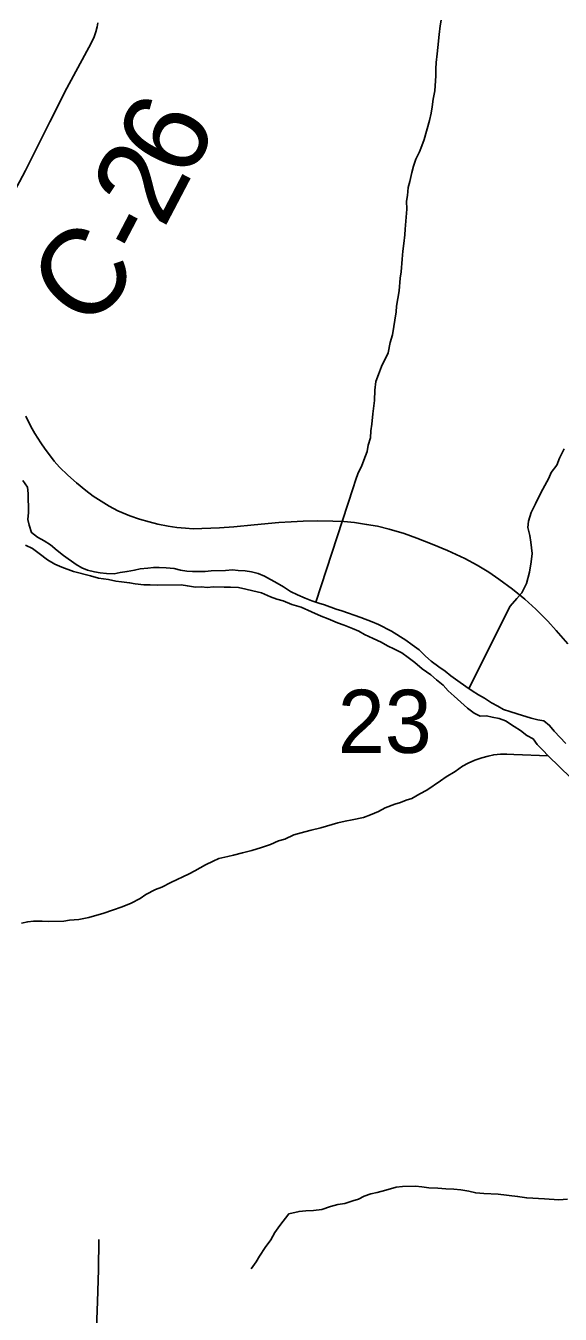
# Model space of a CAD drawing. Extents: x -3.3 to 34, y 0 to 56.8.
# Drawn here: x -2.155 to -1.801, y 31.825 to 32.678 of the extents above; entities that cross this region are included whole.
import ezdxf

# ---------------------------------------------------------------- set-up
doc = ezdxf.new("R2010")
doc.units = 0
for name, color, linetype in [('GM_X_County_Road', 7, 'Continuous'), ('GM_X_Major_River', 7, 'Continuous'), ('GM_X_Section_Text', 7, 'Continuous'), ('GM_X_State_Route', 7, 'Continuous'), ('GM_X_Township_Road', 7, 'Continuous'), ('GT_Project_Soil_Layers', 7, 'Continuous'), ('SH_Masking', 7, 'Continuous')]:
    doc.layers.add(name, color=color, linetype=linetype)

msp = doc.modelspace()

# ---------------------------------------------------------------- linework, layer by layer
at = {"layer": 'GM_X_County_Road'}
msp.add_lwpolyline([(-2.20125, 32.52907), (-2.19752, 32.5329), (-2.19591, 32.53454), (-2.18984, 32.54019), (-2.18704, 32.54282), (-2.17743, 32.55149), (-2.17221, 32.55593), (-2.16814, 32.55999), (-2.16563, 32.56312), (-2.16297, 32.56739), (-2.15867, 32.57507), (-2.15474, 32.58261), (-2.1387, 32.61473), (-2.12751, 32.63716), (-2.11131, 32.667), (-2.10938, 32.67115), (-2.10828, 32.67439), (-2.10742, 32.6777), (-2.1069, 32.68048)], dxfattribs=at)
at = {"layer": 'GM_X_Major_River'}
for points in [[(-2.15654, 32.37711), (-2.15345, 32.3726), (-2.15301, 32.36843), (-2.15284, 32.3559), (-2.15315, 32.35134), (-2.15234, 32.34755), (-2.15076, 32.34263), (-2.14692, 32.33965), (-2.14234, 32.33705), (-2.13813, 32.33445), (-2.13391, 32.33071), (-2.12969, 32.32735), (-2.12127, 32.32139), (-2.11745, 32.31917), (-2.11363, 32.3177), (-2.10907, 32.31662), (-2.10527, 32.31592), (-2.10109, 32.3156), (-2.09616, 32.31529), (-2.092, 32.3161), (-2.08746, 32.31693), (-2.08254, 32.31775), (-2.07876, 32.31857), (-2.07384, 32.31902), (-2.07005, 32.31945), (-2.06626, 32.3195), (-2.06171, 32.31918), (-2.05639, 32.31888), (-2.05221, 32.3178), (-2.04803, 32.3171), (-2.04423, 32.31677), (-2.03589, 32.31689), (-2.03173, 32.31732), (-2.02225, 32.31746), (-2.0177, 32.3179), (-2.01391, 32.31757), (-2.00935, 32.31726), (-2.00517, 32.31656), (-2.00061, 32.31548)], [(-1.79362, 32.18013), (-1.8086, 32.19473), (-1.81207, 32.19848), (-1.81591, 32.20222), (-1.81862, 32.20598), (-1.82282, 32.2082), (-1.82704, 32.21156), (-1.83124, 32.21416), (-1.83698, 32.21788), (-1.84117, 32.21934), (-1.84574, 32.22041), (-1.84954, 32.22112), (-1.85371, 32.22106), (-1.85753, 32.22291), (-1.86212, 32.22626), (-1.87095, 32.23411), (-1.8748, 32.23786), (-1.87826, 32.24161), (-1.88248, 32.24496), (-1.88631, 32.24833), (-1.89206, 32.25243), (-1.89704, 32.25653), (-1.90126, 32.25989), (-1.90547, 32.26288), (-1.91044, 32.26546), (-1.91502, 32.26768), (-1.91922, 32.2699), (-1.92456, 32.27248), (-1.93029, 32.27506), (-1.93411, 32.27729), (-1.93831, 32.27913), (-1.94364, 32.28133), (-1.94821, 32.28279), (-1.95431, 32.28536), (-1.95889, 32.2872), (-1.96538, 32.29014), (-1.97224, 32.29309), (-1.97834, 32.2949), (-1.98406, 32.29748), (-1.98824, 32.29856), (-1.99244, 32.30002), (-1.99854, 32.30259), (-2.00424, 32.30403), (-2.00881, 32.30511), (-2.01375, 32.30618), (-2.01907, 32.30649), (-2.02324, 32.30643), (-2.03045, 32.30671), (-2.03423, 32.30628), (-2.03841, 32.3066), (-2.0422, 32.30654), (-2.04751, 32.30723), (-2.0517, 32.30793), (-2.06762, 32.30771), (-2.07217, 32.30802), (-2.07634, 32.30796), (-2.08204, 32.30864), (-2.08584, 32.30935), (-2.09116, 32.31004), (-2.09495, 32.31036), (-2.0999, 32.31143), (-2.10636, 32.31248), (-2.11169, 32.31393), (-2.1231, 32.31681), (-2.13073, 32.31974), (-2.1353, 32.32158), (-2.14027, 32.32455), (-2.14564, 32.32865), (-2.15023, 32.332), (-2.15481, 32.33422)], [(-2.00061, 32.31548), (-1.99641, 32.31364), (-1.98801, 32.3092), (-1.98381, 32.3066), (-1.97921, 32.30362), (-1.97463, 32.30141), (-1.96967, 32.2992), (-1.9651, 32.29736), (-1.96053, 32.29591), (-1.95672, 32.29482), (-1.9491, 32.29189), (-1.94529, 32.2908), (-1.93272, 32.28642), (-1.92509, 32.28349), (-1.9209, 32.28165), (-1.91249, 32.27721), (-1.90293, 32.27127), (-1.89872, 32.26829), (-1.89413, 32.26493), (-1.8899, 32.26081), (-1.88606, 32.25745), (-1.88108, 32.25372), (-1.87687, 32.25074), (-1.87304, 32.24776), (-1.86844, 32.2444), (-1.86308, 32.24068), (-1.85887, 32.2377), (-1.85466, 32.2351), (-1.85084, 32.23287), (-1.84625, 32.2299), (-1.84205, 32.22768), (-1.83822, 32.22546), (-1.83403, 32.224), (-1.82908, 32.22255), (-1.81994, 32.21964), (-1.81538, 32.21856), (-1.81158, 32.21785), (-1.80774, 32.21487), (-1.80466, 32.21111), (-1.79696, 32.20286)]]:
    msp.add_lwpolyline(points, dxfattribs=at)
at = {"layer": 'GM_X_State_Route'}
msp.add_lwpolyline([(-2.1546, 32.41983), (-2.15116, 32.41293), (-2.14852, 32.40817), (-2.14458, 32.40208), (-2.14179, 32.39789), (-2.13899, 32.39419), (-2.13586, 32.38992), (-2.13217, 32.38588), (-2.12682, 32.38055), (-2.12107, 32.37561), (-2.11491, 32.37043), (-2.10989, 32.36681), (-2.10471, 32.36353), (-2.09928, 32.36016), (-2.09353, 32.35711), (-2.08564, 32.35375), (-2.07931, 32.35144), (-2.07298, 32.34963), (-2.06706, 32.34824), (-2.0604, 32.34692), (-2.05448, 32.34602), (-2.0489, 32.34544), (-2.04371, 32.3452), (-2.02637, 32.34569), (-2.01675, 32.34651), (-2.00327, 32.34782), (-1.987, 32.34931), (-1.97886, 32.3498), (-1.9708, 32.35013), (-1.96151, 32.35029), (-1.95116, 32.35021), (-1.944, 32.34988), (-1.93685, 32.34922), (-1.92888, 32.34807), (-1.92157, 32.34676), (-1.914, 32.34487), (-1.90389, 32.34191), (-1.89551, 32.33895), (-1.88556, 32.33501), (-1.87537, 32.33073), (-1.86386, 32.32539), (-1.85564, 32.32111), (-1.848, 32.31643), (-1.84133, 32.31166), (-1.83221, 32.30508), (-1.82415, 32.29843), (-1.81675, 32.29176), (-1.80878, 32.28387), (-1.80328, 32.27763), (-1.79571, 32.26891)], dxfattribs=at)
at = {"layer": 'GM_X_Township_Road'}
msp.add_lwpolyline([(-2.1239, 31.72935), (-2.11863, 31.73827), (-2.11499, 31.74541), (-2.1134, 31.74949), (-2.11197, 31.75378), (-2.11077, 31.75813), (-2.10993, 31.76182), (-2.10938, 31.76609), (-2.10906, 31.77204), (-2.10837, 31.79717), (-2.10709, 31.83309), (-2.10649, 31.85418), (-2.10613, 31.87429)], dxfattribs=at)
at = {"layer": 'GT_Project_Soil_Layers'}
for points in [[(-1.87939, 32.6822), (-1.8801, 32.67839), (-1.88077, 32.67269), (-1.88179, 32.66393), (-1.88211, 32.65975), (-1.88279, 32.65404), (-1.88312, 32.64986), (-1.88305, 32.6453), (-1.88367, 32.63542), (-1.88474, 32.62971), (-1.88542, 32.62476), (-1.88612, 32.62057), (-1.8872, 32.61562), (-1.89081, 32.60303), (-1.89227, 32.59883), (-1.89374, 32.59501), (-1.89632, 32.59004), (-1.89777, 32.58546), (-1.89885, 32.58127), (-1.90029, 32.57517), (-1.90137, 32.57135), (-1.90168, 32.56603), (-1.90238, 32.56223), (-1.90231, 32.55691), (-1.90296, 32.54892), (-1.90327, 32.5436), (-1.90359, 32.5398), (-1.90427, 32.53409), (-1.90496, 32.52914), (-1.90527, 32.52382), (-1.90591, 32.51545), (-1.90661, 32.51127), (-1.90726, 32.5029), (-1.90901, 32.49262), (-1.90934, 32.48882), (-1.91178, 32.47359), (-1.91323, 32.46863), (-1.91465, 32.46177), (-1.91908, 32.4526), (-1.9209, 32.44725), (-1.92273, 32.44267), (-1.92341, 32.43696), (-1.9237, 32.43012), (-1.92471, 32.42137), (-1.92538, 32.41452), (-1.92607, 32.40996), (-1.92639, 32.40539), (-1.92784, 32.40044), (-1.92854, 32.39625), (-1.93074, 32.39052), (-1.9322, 32.38632), (-1.93441, 32.38211), (-1.93624, 32.37715), (-1.93769, 32.37219), (-1.96247, 32.29653)], [(-1.79813, 32.39807), (-1.80108, 32.39195), (-1.80291, 32.38737), (-1.80663, 32.38238), (-1.80809, 32.37856), (-1.81217, 32.37128), (-1.81438, 32.36708), (-1.81696, 32.36172), (-1.81992, 32.35598), (-1.82174, 32.35026), (-1.82206, 32.34608), (-1.82085, 32.34078), (-1.82003, 32.33623), (-1.81917, 32.32865), (-1.81985, 32.32332), (-1.82089, 32.31647), (-1.82306, 32.30884), (-1.82601, 32.30272), (-1.82937, 32.29888), (-1.83385, 32.29388), (-1.8611, 32.23928)], [(-2.15745, 32.0839), (-2.15329, 32.08471), (-2.1495, 32.08515), (-2.14381, 32.08522), (-2.13926, 32.08491), (-2.1294, 32.08505), (-2.12562, 32.08586), (-2.11956, 32.08632), (-2.11275, 32.08756), (-2.10293, 32.09035), (-2.09727, 32.09233), (-2.09086, 32.0947), (-2.08482, 32.09706), (-2.0788, 32.10018), (-2.07505, 32.1029), (-2.06864, 32.10602), (-2.06449, 32.1076), (-2.05847, 32.11072), (-2.04642, 32.11659), (-2.04265, 32.11854), (-2.0355, 32.12244), (-2.0306, 32.12478), (-2.02684, 32.12674), (-2.02079, 32.12796), (-2.01701, 32.12877), (-2.01096, 32.13037), (-2.00492, 32.13198), (-1.9985, 32.13397), (-1.99246, 32.13595), (-1.98718, 32.1383), (-1.98303, 32.1395), (-1.977, 32.14224), (-1.96982, 32.14424), (-1.96567, 32.14544), (-1.95924, 32.14705), (-1.94791, 32.15025), (-1.943, 32.15145), (-1.93846, 32.15228), (-1.9309, 32.1539), (-1.92637, 32.15548), (-1.92109, 32.15783), (-1.91658, 32.16018), (-1.91016, 32.16255), (-1.90639, 32.16374), (-1.90262, 32.16531), (-1.89884, 32.1665), (-1.89358, 32.16961), (-1.88906, 32.17195), (-1.88004, 32.17816), (-1.87629, 32.18087), (-1.87027, 32.18437), (-1.86539, 32.18785), (-1.86162, 32.18981), (-1.8571, 32.19177), (-1.85257, 32.19335), (-1.84842, 32.19455), (-1.84464, 32.19536), (-1.84009, 32.19581)], [(-1.84009, 32.19581), (-1.83592, 32.19586), (-1.83137, 32.19555), (-1.80866, 32.19479)], [(-2.0053, 31.85477), (-2.00195, 31.85937), (-1.99973, 31.8632), (-1.99602, 31.86895), (-1.99229, 31.87393), (-1.9897, 31.8789), (-1.98635, 31.88351), (-1.98039, 31.89119), (-1.97359, 31.8928), (-1.96905, 31.89324), (-1.96412, 31.89331), (-1.95844, 31.89415), (-1.95278, 31.89613), (-1.94787, 31.89734), (-1.94333, 31.89816), (-1.93804, 31.89975), (-1.93427, 31.90094), (-1.9305, 31.9029), (-1.92597, 31.90448), (-1.92181, 31.90529), (-1.91615, 31.90689), (-1.90935, 31.90889), (-1.90518, 31.90933), (-1.89646, 31.90945), (-1.89229, 31.90913), (-1.88773, 31.90843), (-1.88166, 31.90814), (-1.87634, 31.90783), (-1.87103, 31.90753), (-1.86648, 31.90721), (-1.86116, 31.90614), (-1.85659, 31.90507), (-1.85128, 31.90476), (-1.84179, 31.90414), (-1.82888, 31.9028), (-1.8228, 31.90175), (-1.81104, 31.90115), (-1.80155, 31.90052), (-1.79587, 31.90098)]]:
    msp.add_lwpolyline(points, dxfattribs=at)

# ---------------------------------------------------------------- texts
at = {"layer": 'GM_X_Section_Text'}
msp.add_text('23', height=0.041856, rotation=0.00001, dxfattribs=at).set_placement((-1.94798, 32.19661))
at = {"layer": 'SH_Masking'}
for s, rotation, p in [('6', 63.06796, (-2.04665, 32.57496)), ('2', 62.3527, (-2.06325, 32.54326)), ('-', 62.38795, (-2.07406, 32.5226)), ('C', 47.39892, (-2.11496, 32.475))]:
    msp.add_text(s, height=0.05682, rotation=rotation, dxfattribs=at).set_placement(p)

doc.saveas('drawing.dxf')
